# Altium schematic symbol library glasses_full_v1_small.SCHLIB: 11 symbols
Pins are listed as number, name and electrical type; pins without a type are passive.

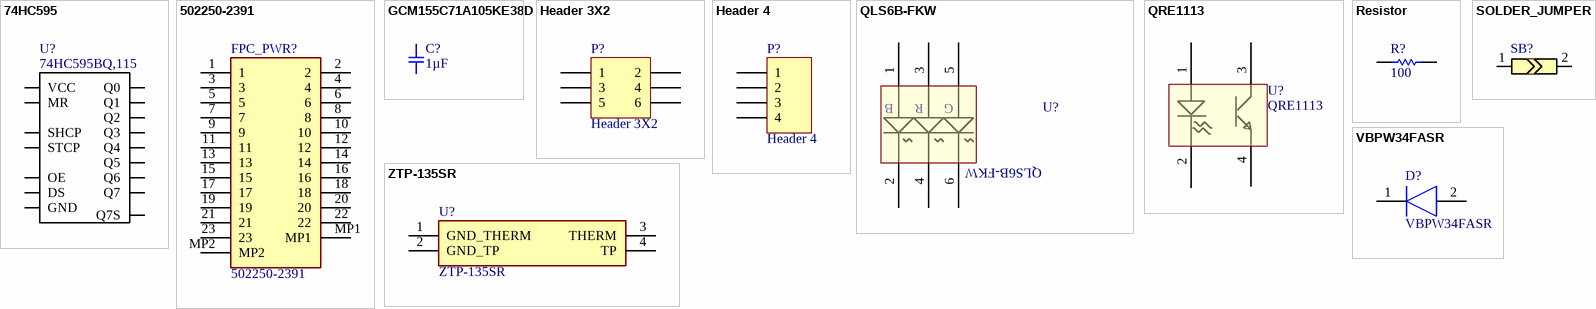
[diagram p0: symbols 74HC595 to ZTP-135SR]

## 74HC595
designator U?, comment 74HC595BQ,115
MF: STMicroelectronics; MP: 74HC165
footprint SO-16
footprint QFN50P250X350X100-17N
footprint 74VHC595 - QFN127P600-8N
pins: 1 Q1 (io), 2 Q2 (io), 3 Q3 (io), 4 Q4 (io), 5 Q5 (io), 6 Q6 (io), 7 Q7 (io), 8 GND (io), 9 Q7S (io), 10 MR (io), 11 SHCP (io), 12 STCP (io), 13 OE (io), 14 DS (io), 15 Q0 (io), 16 VCC (io)

## 502250-2391
designator FPC_PWR?
Connector; Manufacturer_Name: Molex
footprint 5022502391
footprint 5022502391
pins: 1, 2, 3, 4, 5, 6, 7, 8, 9, 10, 11, 12, 13, 14, 15, 16, 17, 18, 19, 20, 21, 22, 23, MP1, MP2

## GCM155C71A105KE38D
designator C?, comment 1µF
CAP CER 1UF 10V X7S 0402; Part Number: GCM155C71A105KE38D; Manufacturer: Murata Electronics North America; Factory Stock: 0; Unit Price (USD): 0.12; Minimum Quantity: 1; Tolerance: ±10%
footprint SMD-0402C
footprint 0402C
pins: 1, 2

## Header 3X2
designator P?
Header, 3-Pin, Dual row
footprint HDR2X3 (Connector; Header; 3x2 Position)
signal-integrity model Connector
footprint HEADER_PROGRAM_STLINK_SWD
pins: 1, 2, 3, 4, 5, 6

## Header 4
designator P?
Header, 4-Pin
footprint HDR1X4 (Connector; Header; 4 Position)
signal-integrity model Connector
pins: 1, 2, 3, 4

## QLS6B-FKW
designator U?  (value not drawn)
CREE RGB LED
footprint QLS6B-FKW (CREE RBG LED RIGHT ANGLE)
pins: 1 B_A, 2 B_C, 3 R_A, 4 R_C, 5 G_A, 6 G_C

## QRE1113
designator U?
IR Emitter and Receiver
footprint QRE1113_DIP (QRE1113 IR PHOTODIODE/TRANSISTOR PAIR)
pins: 1, 2, 3, 4

## Resistor
designator R?, comment 100
footprint 0603 (0603 generic chip component)
footprint 0402R
footprint AXIAL-0.3
footprint 1210R (Chip Resistor, 2-Leads, Body 3.2x2.5mm, IPC Medium Density)
footprint RESC3216M (Chip Resistor, Body 3.2x1.6mm, IPC Low Density)
footprint 1206R (Chip Resistor, Body 3.2x1.6mm, IPC Low Density)
footprint 1206R_WIDE
simulation model RESISTOR (Resistor)
footprint 0603R (0603 Capacitor)
footprint RN55D (Mil-spec metal film resistor)
footprint RN60D (Mil-spec metal film resistor)
pins: 1, 2

## SOLDER_JUMPER
designator SB?  (value not drawn)
footprint JUMPER_SMD
footprint SMD_JUMPER
pins: 1, 2 1

## VBPW34FASR
designator D?
Diode; Manufacturer_Name: Vishay
footprint VBPW34FASR
footprint VBPW34FAS (IR Photodiode SMD (Vive))
pins: 1 A, 2 K

## ZTP-135SR
designator U?
Undefined or Miscellaneous; Manufacturer_Name: Amphenol Advanced Sensors; Allied_Number: 70282698
footprint ZTP-135SR
footprint ZTP-135SR
pins: 1 GND_THERM, 2 GND_TP, 3 THERM, 4 TP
